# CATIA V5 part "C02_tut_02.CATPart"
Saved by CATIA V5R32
Part number: Part1
Bounding box of the stored display mesh (mm): x 0 to 20, y -60 to 60, z -50 to 50
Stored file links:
  D:\PROJECTS\Project 2022\CATIA V5 6R 2022\Resources\Tutorial Files\c02_catia_v5_6r2021_tut\C02_tut_02.CATPart
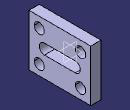
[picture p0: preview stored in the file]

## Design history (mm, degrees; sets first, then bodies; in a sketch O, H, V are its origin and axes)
Body1 (main body)
  Sketch1 on yz-plane, origin (0, 0, 0), H (0, 1, 0), V (0, 0, 1)
    line L1 (-60, -50) -> (60, -50)
    line L2 (60, -50) -> (60, 50)
    line L3 (60, 50) -> (-60, 50)
    line L4 (-60, 50) -> (-60, -50)
    line L5 (-30, 10) -> (30, 10)
    arc A1 centre (30, 0) radius 10 from (30, 10) to (30, -10) cw
    line L6 (30, -10) -> (-30, -10)
    arc A2 centre (-30, 0) radius 10 from (-30, -10) to (-30, 10) cw
    circle A3 centre (40, -30) radius 10
    circle A4 centre (40, 30) radius 10
    circle A5 centre (-40, 30) radius 10
    circle A6 centre (-40, -30) radius 10
    radius A3 = 10
    radius A4 = 10
    radius A6 = 10
    horizontal: L1 H, L3 H, L5 H
    vertical: L2 V, L4 V
    tangency: A1 L5, L6 A1, A2 L6
  Pad1: profile Sketch1, direction (1, 0, 0), length 20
